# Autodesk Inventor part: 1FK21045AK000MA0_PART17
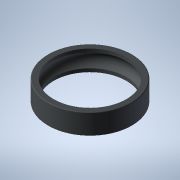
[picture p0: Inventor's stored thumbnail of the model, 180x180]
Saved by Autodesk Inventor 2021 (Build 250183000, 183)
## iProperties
Created: 2025-04
Part Number: 1FK21045AK000MA0_PART17
Material: Generic
Catalog Web Link: www.3dfindit.com
Description: -Servo synchronous motor
Document SubType Name: Modeling
Designer: psAdmin
Mass: 1.64389 g
Surface Area: 26.4305 cm^2
Volume: 1.64389 cm^3
Density: 1 g/cm^3
Appearance: PSOLRGB-212-217-219
Category: PARTsolutions
Title: 1FK21045AK000MA0_PART17
Author: Cadenas PARTsolutions
Comments: Servo synchronous motor
Sending System: PARTsolutions
Preprocessor: ST-DEVELOPER v19.3
PSOL_IDENT_0: {$CADENAS_DATA/23d-libs/siemens_ag/_cat_/3d/2f/1fk21045ak000ma0.prj},216 {VTYP=3D},{NB=1FK21045AK000
PSOL_IDENT_1: MA0_PART17},{LINA=1FK21045AK000MA0_PART17},{NN=1FK21045AK000MA0_PART17},{NOPRJ=TRUE},{DATE=19.08.202
PSOL_IDENT_2: 5 14:00:34},{GEOMDATE=30.07.2025 02:01:24},{VERSION=},{LINEID=10},{WBVAR=},{WBNUMERIC=}  {NB=1FK2104
PSOL_IDENT_3: 5AK000MA0_PART17},{LINA=1FK21045AK000MA0_PART17},{KT=DUMMY},{PREVIEW=../../../_pool_/a9/69/p_d211_xx
PSOL_IDENT_4: _00818j.png},{DESCSHORT=SIMOTICS S-1FK2 HD, SINAMICS S210 3AC 400V-480V, 1.7 Nm, 6000 rpm},{DESCLONG=
PSOL_IDENT_5: SIMOTICS S-1FK2 HD servo motor M0=2.4 Nm; PN = 1.07 kW at nN=6000 rpm (380-480 V); PN = 0.75 kW at n
PSOL_IDENT_6: N=3000 rpm (200-240 V); degree of protection IP64; cylindrical shaft D19x40mm; absolute encoder 22-b
PSOL_IDENT_7: it + 12-bit multiturn (encoder AM22DQC); with OCC interface; plug size M17, rotatable; SIMOTICS S-1F
PSOL_IDENT_8: K2 servomotorfor a wide range of uses in industrial environments. SIMOTICS S‑1FK2 servomotors are co
PSOL_IDENT_9: mpact synchronous motors with a high dynamic performance that set themselves apart as a result of th
PSOL_IDENT_10: eir high power density, degree of protection and overload capability. The motors are available in tw
PSOL_IDENT_11: o variants: as High Dynamic variant (highest dynamic performance as a result of the low intrinsic mo
PSOL_IDENT_12: ment of inertia for applications demanding a high dynamic performance with low moved masses) - and a
PSOL_IDENT_13: s Compact variant (precise and stable closed-loop control for medium up to large moved masses as a r
PSOL_IDENT_14: esult of a medium intrinsic moment of inertia). SIMOTICSS‑1FK2 servomotors fully exploit their stren
PSOL_IDENT_15: gths in a system with the SINAMICSS210 frequency converter and simple connection using the one cable
PSOL_IDENT_16: connection (OCC). Advantages include the short control and positioning times, fast and precise corr
PSOL_IDENT_17: ection of disturbing quantities as well as stable control with a high dynamic performance. The servo
PSOL_IDENT_18: motors can be configured to address a wide range of requirements. For example with and without hold
PSOL_IDENT_19: ing brake, IP64 or IP65 degree of protection, singleturn or multiturn absolute encoders - to name ju
PSOL_IDENT_20: st a few. Further, the servomotors are available in different shaft heights extending from 20 to 100
PSOL_IDENT_21: . A shaft sealing ring is available to achieve an IP65 degree of protection and for subsequent mount
PSOL_IDENT_22: ing at the motor or as spare part. SIMOTICS - the optimum motor for each and every motion control ap
PSOL_IDENT_23: plication.},{INTNO=804766789342},{SUPPLIERALTNO=1FK2104-5AK00-0MA0},{MANUID=1FK21045AK000MA0},{MANUN
PSOL_IDENT_24: AME=Siemens},{MANUTYPEDESC=Synchronous motor 1FK2-HD 2,39 Nm},{AAU732=SIMOTICS},{AAO057=S-1FK2},{AAU
PSOL_IDENT_25: 734=SIMOTICS S-1FK2 HD servo motor M0=2.4 Nm; PN = 1.07 kW at nN=6000 rpm (380-480 V); PN = 0.75 kW
PSOL_IDENT_26: at nN=3000 rpm (200-240 V); degree of protection IP64; cylindrical shaft D19x40mm; absolute encoder
PSOL_IDENT_27: 22-bit + 12-bit multiturn (encoder AM22DQC); with OCC interface; plug size M17, rotatable;},{AAW338=
PSOL_IDENT_28: Synchronous motor 1FK2-HD 2,39 Nm},{AAO742=SIMOTICS},{AAO663=4042948691151},{NOCUPEROU=1},{PRICEQUAN
PSOL_IDENT_29: TITY=1},{QUANTITYMIN=1},{QUANTITYINT=1},{CTN=85015100},{COO=DE},{AAO676=1FK2104-5AK00-0MA0},{AAO677=
PSOL_IDENT_30: Siemens AG},{ORDERUNIT=C62},{CONTENTUNIT=C62}
NB: 1FK21045AK000MA0_PART17
NT: Servo synchronous motor
NBSYN: $MANUID._PART17
LINA: 1FK21045AK000MA0_PART17
CATALOG: SIEMENS
PREVIEW: ../../../_pool_/a9/69/p_d211_xx_00818j.png
DESCSHORT: SIMOTICS S-1FK2 HD, SINAMICS S210 3AC 400V-480V, 1.7 Nm, 6000 rpm
DESCLONG: SIMOTICS S-1FK2 HD servo motor M0=2.4 Nm; PN = 1.07 kW at nN=6000 rpm (380-480 V); PN = 0.75 kW at nN=3000 rpm (200-240 V); degree of protection IP64; cylindric
INTNO: 804766789342
SUPPLIERALTNO: 1FK2104-5AK00-0MA0
MANUID: 1FK21045AK000MA0
MANUNAME: Siemens
MANUTYPEDESC: Synchronous motor 1FK2-HD 2,39 Nm
AAU732: SIMOTICS
AAO057: S-1FK2
AAU734: SIMOTICS S-1FK2 HD servo motor M0=2.4 Nm; PN = 1.07 kW at nN=6000 rpm (380-480 V); PN = 0.75 kW at nN=3000 rpm (200-240 V); degree of protection IP64; cylindric
AAW338: Synchronous motor 1FK2-HD 2,39 Nm
AAO742: SIMOTICS
AAO663: 4042948691151.0
NOCUPEROU: 1
PRICEQUANTITY: 1
QUANTITYMIN: 1
QUANTITYINT: 1
CTN: 85015100
COO: DE
ARTICLENO: 1FK21045AK000MA0_PART17
BOMINFO: 1FK21045AK000MA0_PART17
CREATOR: CADENAS GmbH
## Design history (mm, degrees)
feature "2025_04_17_15_39_51_0728"
body "Solid1"
